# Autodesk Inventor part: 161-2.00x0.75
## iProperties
Created: 2007-06
Part Number: 161-2.00x0.75
Document SubType Name: Modeling
Designer: btaylor
Density: 1 g/cm^3
Author: btaylor
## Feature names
1. Extrusion1
2. Extrusion2
3. Extrusion3
4. Extrusion4
5. Extrusion5
6. Fillet1
7. Fillet2
8. Fillet3
9. Fillet4
10. Extrusion6
11. Extrusion7
12. Extrusion8
13. Extrusion9
14. Extrusion10
15. Fillet7
16. Fillet8
17. Chamfer1
18. Chamfer2
19. Chamfer3
20. Fillet9
21. Fillet10
22. Fillet11
23. Fillet12
24. Fillet13
